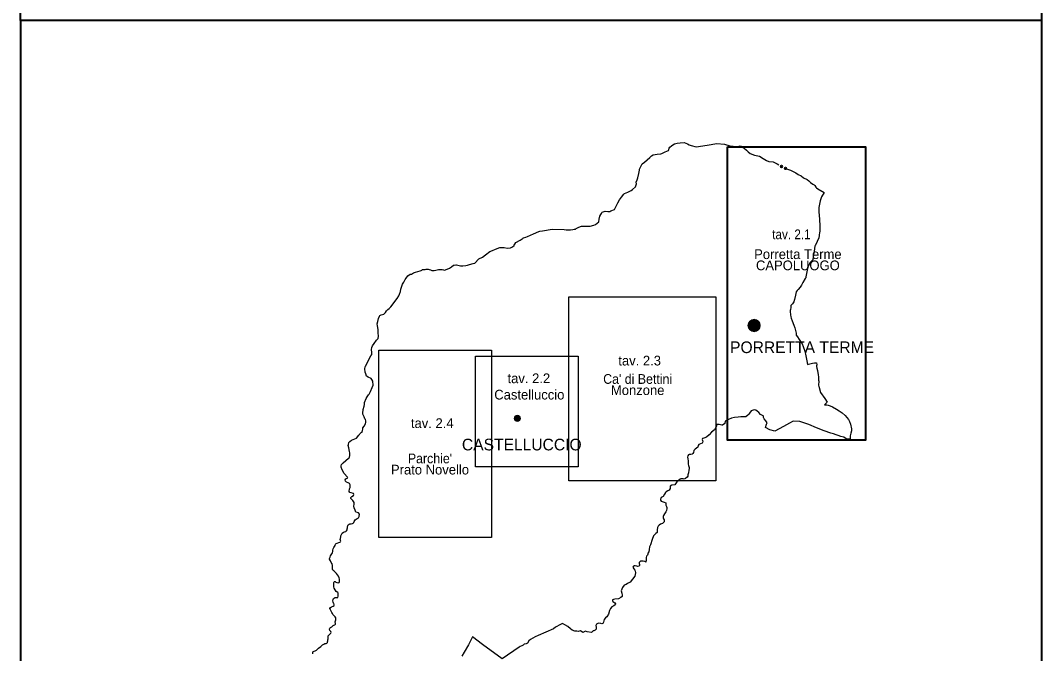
# Model space of a CAD drawing. Extents: x 654952 to 658955, y 890426 to 894481.
# Drawn here: x 654952 to 656002, y 892344 to 892994 of the extents above; entities that cross this region are included whole.
import ezdxf
from ezdxf.enums import TextEntityAlignment as Align

# ---------------------------------------------------------------- set-up
doc = ezdxf.new("R2010")
doc.units = 0
doc.header["$LTSCALE"] = 4
doc.header["$PDMODE"] = 32
doc.header["$PDSIZE"] = 2
doc.layers.add('60', color=7, linetype='Continuous', lineweight=35)

msp = doc.modelspace()

# ---------------------------------------------------------------- hatches: boundary and pattern name
at = {"layer": '60'}
for points in [[(655712.93, 892680.92, 1), (655700.21, 892680.92, 1)], [(655466.32, 892585.43, 1), (655459.96, 892585.43, 1)]]:
    msp.add_hatch(color=256, dxfattribs=at).paths.add_polyline_path(points)

# ---------------------------------------------------------------- linework, layer by layer
at = {"layer": '60', "lineweight": 40}
for p, q in [((654952.15, 892994.48), (654952.15, 890425.88)), ((656002.15, 892994.48), (656002.15, 890425.88))]:
    msp.add_line(p, q, dxfattribs=at)
for points in [[(656002.16, 894480.73), (656002.16, 892994.48), (654952.16, 892994.48), (654952.16, 894480.73)], [(655679.1, 892864.47), (655821.19, 892864.47), (655821.19, 892562.94), (655679.1, 892562.94)]]:
    msp.add_lwpolyline(points, close=True, dxfattribs=at)
at = {"layer": '60', "lineweight": 25}
for points in [[(655584.45, 892823.6), (655585.67, 892826.68), (655585.43, 892828.31), (655586.45, 892830.79), (655586.97, 892832.8), (655588.11, 892837.24), (655588.71, 892840.72), (655588.71, 892841.76), (655590.09, 892844.31), (655591.57, 892847.08), (655593.99, 892848.64), (655599.29, 892853.67), (655601.07, 892855.27), (655602.93, 892856.43), (655606.73, 892856.88), (655610.49, 892857.48), (655611.67, 892857.71), (655615.05, 892859.43), (655618.37, 892860.87), (655619.19, 892863.04), (655619.97, 892864.15), (655621.47, 892865.43), (655622.95, 892866.59), (655624.79, 892867.48), (655627.29, 892868.36), (655630.63, 892868.71), (655634.61, 892869), (655638.05, 892867.56), (655639.95, 892866.71), (655641.71, 892865.99), (655646.85, 892864.59), (655658.25, 892866.28), (655668.21, 892867.92), (655676.23, 892867.47), (655681.53, 892865.52), (655684.87, 892865.27), (655689.69, 892864.91), (655692.33, 892865.47), (655693.29, 892865.4), (655694.19, 892865)], [(655694.19, 892865), (655695.09, 892864.39), (655696.41, 892863.15), (655698.65, 892861.04), (655700.37, 892859.35), (655702.65, 892857.87), (655706.85, 892856.16), (655712.25, 892855.04), (655715.85, 892852.63), (655719.39, 892850.47), (655721.85, 892849.32), (655726.11, 892849.03), (655730.19, 892847.12), (655731.83, 892845.95)], [(655738.93, 892842.44), (655743.87, 892840.64), (655747.47, 892838.75), (655749.57, 892837.72), (655751.97, 892836.28), (655754.79, 892834.67), (655757.49, 892832.8), (655761.03, 892830.96), (655762.95, 892829.52), (655764.49, 892827.83), (655766.97, 892826.32), (655768.35, 892825.56), (655768.89, 892824.72), (655770.05, 892823.04), (655770.57, 892822.52), (655772.15, 892821.51), (655778.61, 892817.76), (655776.03, 892813.08), (655775.19, 892811.23), (655774.49, 892809.12), (655773.21, 892802.16), (655773.27, 892797.16), (655773.59, 892794.72), (655773.75, 892789.6), (655773.91, 892787.72), (655774.13, 892785.31), (655774.11, 892778.2), (655773.69, 892775.79), (655773.53, 892774.55), (655773.47, 892773.15), (655773.27, 892771.39), (655773.11, 892770.87), (655771.53, 892767.36), (655769.45, 892762.68), (655769.03, 892762.6), (655768.29, 892757.32), (655767.99, 892755.75), (655767.79, 892753.47), (655767.35, 892751.23), (655767.03, 892749.24)], [(655486.17, 892777.83), (655489.09, 892778.35), (655498.79, 892779.88), (655511.17, 892779.51), (655513.21, 892779.36), (655517.61, 892779.15), (655520.11, 892779.6), (655521.59, 892780), (655522.91, 892780.07), (655523.73, 892780.76), (655526.49, 892782.03), (655529.09, 892782.88), (655530.45, 892783.12), (655532.97, 892783.19), (655536.29, 892783.19), (655538.13, 892783.19), (655541.65, 892784.2), (655543.43, 892784.68), (655545.03, 892786.08), (655547.01, 892787.56), (655547.37, 892790.32), (655548.03, 892793.28), (655548.97, 892795.12), (655549.77, 892796.19), (655550.43, 892797.4), (655553.33, 892798.44), (655556.19, 892798.2), (655558.27, 892798.15), (655559.41, 892798.72), (655562.85, 892800.04), (655564.35, 892802.83), (655566.49, 892806.87), (655568.09, 892810.03), (655570.11, 892812.87), (655572.61, 892815.92), (655573.39, 892816.48), (655576.83, 892818.12), (655579.99, 892819.8), (655581.65, 892820.55), (655584.45, 892823.6)], [(655388.37, 892737.79), (655390.95, 892738.79), (655393.31, 892739.83), (655395.29, 892741.39), (655397.33, 892742.92), (655398.21, 892743), (655399.95, 892743.28), (655400.59, 892743.24), (655404.53, 892742.12), (655405.17, 892742.12), (655406.91, 892742.39), (655410.21, 892742.63), (655411.95, 892743), (655413.99, 892743.55), (655417.55, 892744.55), (655419.33, 892745.08), (655423.53, 892749.31), (655427.43, 892751.28), (655430.49, 892753.44), (655434.75, 892757.04), (655437.57, 892757.92), (655440.75, 892759.27), (655445.01, 892761.12), (655445.71, 892761.16), (655449.53, 892761), (655452.79, 892760.44), (655456.23, 892760.75), (655458.21, 892761.67), (655459.87, 892763.04), (655459.81, 892763.52), (655460.57, 892764.64), (655461.73, 892766.07), (655465.93, 892768.48), (655469.01, 892770.64), (655469.23, 892771.19), (655471.95, 892771.55), (655473.45, 892772.32), (655479.69, 892775.04), (655485.35, 892777.55), (655486.17, 892777.83)], [(655767.03, 892749.24), (655766.83, 892748.55), (655765.89, 892747.56), (655764.89, 892746.48), (655764.25, 892745.6), (655763.51, 892744.55), (655762.51, 892742.24), (655761.97, 892740.88), (655761.27, 892737.95), (655760.59, 892734.51), (655759.85, 892730.83), (655759.59, 892730.03), (655759.05, 892729.12), (655756.79, 892725.11), (655755.21, 892722.39), (655753.85, 892720.4), (655751.75, 892717.87), (655750.85, 892716.75), (655749.83, 892715.52), (655749.07, 892712.11), (655748.05, 892707.76), (655747.41, 892705.15), (655745.89, 892703.31), (655744.47, 892701.39), (655744.47, 892701), (655744.41, 892699.32), (655743.85, 892697.23), (655743.59, 892696.24), (655743.71, 892695.31), (655743.97, 892691.91), (655744.23, 892689.99), (655744.73, 892688.56), (655745.69, 892685.84), (655747.29, 892681.44), (655748.43, 892678.67), (655749.97, 892673.15), (655749.97, 892672.39), (655749.71, 892671.15), (655751.13, 892669.36), (655752.91, 892666.63)], [(655339.59, 892708.6), (655341.21, 892711.39), (655341.97, 892713.12), (655342.85, 892716.03), (655343.43, 892718.28), (655344.19, 892721.24), (655345.13, 892723.55), (655346.23, 892725.52), (655347.75, 892728.12), (655348.83, 892729.68), (655350.39, 892731.91), (655353.05, 892733.52), (655354.21, 892733.76), (655355.23, 892734.39), (655356.25, 892735.12), (655358.31, 892735.75), (655363.09, 892737.24), (655364.31, 892737.6), (655364.81, 892737.96), (655365.63, 892738.6), (655366.29, 892738.6), (655367.47, 892738.35), (655368.17, 892738.35), (655369.45, 892738.79), (655371.57, 892738.92), (655372.53, 892738.6), (655373.67, 892738.11), (655375.27, 892737.6), (655376.49, 892737.36), (655377.57, 892737.36), (655379.23, 892737.72), (655380.63, 892738.11), (655382.17, 892738.48), (655383.37, 892738.55), (655384.15, 892738.55), (655385.73, 892738.35), (655387.21, 892738.23), (655388.37, 892737.79)], [(655314.39, 892623.75), (655313.37, 892625.55), (655312.75, 892626.6), (655309.55, 892627.83), (655308.03, 892628.68), (655307.37, 892631.36), (655306.75, 892633.03), (655306.41, 892636.36), (655306.67, 892638.36), (655307.07, 892639.23), (655312.49, 892649.88), (655313.45, 892651.12), (655313.49, 892651.95), (655313.37, 892653.19), (655313.05, 892656.11), (655313.63, 892658.28), (655314.21, 892660), (655315.93, 892662.28), (655318.41, 892665.76), (655320.01, 892667.68), (655320.39, 892670.04), (655320.15, 892673.44), (655319.89, 892676.92), (655319.19, 892680.44), (655319.11, 892682.56), (655319.49, 892685.16), (655320.21, 892688.2), (655321.23, 892690.63), (655321.73, 892691.07), (655323.15, 892691.8), (655325.75, 892692.6), (655326.57, 892693.11), (655327.53, 892694.28), (655328.61, 892695.88), (655329.83, 892697.51), (655331.37, 892698.56), (655333.15, 892699.99), (655335.57, 892703.2), (655337.31, 892705.44), (655339.59, 892708.6)], [(655752.91, 892666.63), (655755.83, 892661.92), (655756.85, 892659.27), (655758.71, 892654.56), (655759.73, 892649.87), (655760.87, 892644.59), (655761.45, 892640.92), (655762.59, 892641.28), (655766.73, 892642.28), (655768.79, 892642.67), (655770.57, 892642.55), (655771.01, 892640.36), (655770.83, 892639.44), (655770.69, 892638.88), (655771.15, 892637.2), (655771.71, 892634.68), (655772.17, 892632.44), (655772.43, 892630.47), (655772.67, 892627.99), (655772.93, 892624.59), (655773.13, 892623.6), (655772.81, 892619.68), (655772.99, 892618.36), (655773.45, 892617.63), (655773.39, 892617.07), (655774.97, 892612.12), (655779.39, 892605.8), (655781.61, 892602.11), (655778.97, 892599.36), (655780.39, 892599.31), (655781.39, 892599.4), (655782.75, 892599.08), (655784.79, 892598.39), (655787.05, 892597.36), (655791.39, 892594.95), (655793.99, 892593.32), (655797.13, 892591.16), (655800.05, 892588.56), (655802.03, 892586.24), (655803.69, 892584.32)], [(655290.97, 892550.04), (655290.65, 892551.52), (655289.69, 892555.12), (655289.31, 892557.72), (655289.37, 892558.59), (655290.01, 892560.64), (655290.91, 892561.68), (655292.57, 892563.12), (655295.89, 892564.48), (655297.73, 892565.16), (655300.17, 892568.12), (655300.87, 892568.88), (655301.31, 892569.55), (655302.53, 892570.8), (655303.41, 892571.23), (655303.55, 892572.04), (655303.93, 892573.03), (655304.07, 892574.52), (655304.31, 892575.88), (655305.53, 892577.6), (655306.95, 892579.91), (655307.25, 892581.59), (655307.25, 892582.8), (655306.95, 892584.16), (655306.43, 892585.16), (655305.53, 892587.04), (655304.25, 892589.83), (655304.13, 892590.95), (655304.63, 892594.55), (655305.59, 892598), (655306.05, 892599.68), (655305.99, 892601.67), (655307.63, 892605.88), (655308.79, 892607.75), (655310.07, 892609.67), (655310.83, 892610.32), (655312.11, 892613.19), (655313.77, 892617.08), (655314.99, 892619.76), (655314.39, 892623.75)], [(655703.39, 892593.28), (655701.69, 892590.96), (655701.15, 892589.64), (655700.01, 892588.6), (655698.23, 892587), (655697.21, 892586.95), (655693.97, 892587.03), (655692.81, 892586.95), (655690.03, 892586.56), (655686.43, 892586.28), (655683.15, 892585.63), (655680.17, 892584.44), (655676.77, 892582.68), (655676.37, 892580.04), (655674.19, 892578.44), (655673.25, 892578.64), (655670.73, 892579.19), (655668.33, 892579.24), (655667.47, 892576.87), (655665.83, 892573.76), (655662.91, 892571.32), (655660.19, 892568.64), (655657.67, 892566.32), (655655.01, 892565.2), (655653.35, 892564.63), (655653.09, 892563.59), (655653.57, 892562.79), (655653.89, 892561.2), (655653.29, 892560.15), (655651.39, 892559.36), (655649.61, 892558.56), (655649.13, 892557.64), (655648.73, 892555.87), (655647.49, 892554.76), (655645.97, 892553.87), (655645.11, 892553.2), (655644.57, 892552.31), (655644.27, 892550.44), (655643.59, 892549.36), (655642.85, 892548.71)], [(655803.69, 892584.32), (655804.59, 892582.35), (655805.61, 892579.68), (655806.87, 892574.84), (655806.75, 892572.79), (655806.13, 892570.43), (655805.45, 892567.36), (655805.17, 892564.55), (655803.15, 892563.96), (655801.23, 892564.6), (655798.93, 892566.07), (655795.87, 892566.84), (655793.15, 892567.92), (655790.97, 892568.56), (655788.19, 892569.68), (655785.39, 892570.43), (655778.61, 892572.6), (655770.71, 892575.63), (655762.83, 892579.08), (655753.71, 892582.32), (655746.63, 892582.44), (655743.11, 892580.47), (655736.85, 892577.19), (655727.75, 892572.48), (655722.87, 892573.83), (655718.31, 892576.08), (655719.41, 892579.48), (655720.09, 892580.95), (655718.67, 892583.04), (655717.03, 892585.03), (655716.21, 892586.48), (655716.21, 892587.8), (655715.87, 892587.95), (655713.29, 892589.52), (655711.33, 892591.63), (655709.69, 892592.95), (655708.33, 892594), (655706.97, 892594.2), (655705.51, 892593.95), (655703.39, 892593.28)], [(655298.31, 892488.84), (655297.11, 892489.2), (655296.21, 892491.27), (655295.25, 892493.48), (655294.93, 892495.28), (655295.37, 892497.4), (655295.37, 892498.88), (655293.85, 892500.99), (655291.93, 892502.96), (655291.75, 892504.03), (655292.83, 892505.03), (655294.61, 892506.07), (655295.07, 892507.36), (655294.49, 892508.24), (655292.31, 892508.92), (655290.71, 892509.28), (655290.27, 892510.28), (655290.53, 892512.88), (655291.17, 892514.32), (655291.05, 892517.07), (655290.39, 892518.67), (655289.25, 892519.28), (655287.47, 892519.79), (655286.31, 892521.03), (655285.93, 892522.27), (655286.69, 892523.39), (655288.29, 892523.92), (655288.81, 892524.36), (655288.35, 892525.12), (655285.11, 892528.96), (655282.87, 892532.43), (655281.79, 892535.4), (655281.79, 892536.83), (655282.47, 892538.2), (655283.87, 892539.88), (655286.75, 892542.16), (655289.49, 892544.4), (655290.57, 892545.28), (655290.91, 892547.68), (655290.97, 892550.04)], [(655642.85, 892548.71), (655641.45, 892548.32), (655639.93, 892548.28), (655639.25, 892548.08), (655638.51, 892547), (655638.13, 892545.76), (655638.41, 892543.96), (655638.87, 892541.99), (655638.93, 892540.4), (655638.93, 892538.32), (655639.07, 892537.08), (655639.41, 892536.04), (655639.71, 892535.07), (655639.71, 892533.79), (655639.55, 892532.36), (655638.97, 892529.52), (655638.33, 892527.36), (655638.39, 892525.92), (655637.71, 892524.99), (655636.13, 892523.84), (655634.67, 892523.15), (655633.55, 892523.28), (655631.21, 892523.28), (655630.39, 892522.95), (655628.33, 892521.35), (655627.11, 892520.24), (655625.07, 892517.32), (655621.85, 892516.95), (655620.33, 892515.67), (655620.29, 892513.35), (655619.37, 892511.75), (655617.75, 892510.88), (655616.25, 892510.03), (655615.37, 892509.27), (655614.31, 892507.47), (655613.03, 892505.2), (655612.21, 892504.72), (655611.13, 892504), (655610.55, 892503.27), (655610.31, 892502.4)], [(655610.31, 892502.4), (655610.35, 892501.51), (655611.09, 892500.28), (655611.91, 892500), (655613.97, 892499.43), (655615.71, 892498.63), (655615.91, 892497.07), (655615.95, 892496.11), (655616.49, 892494.95), (655616.79, 892493.8), (655616.79, 892492.91), (655616.45, 892490.68), (655615.81, 892489.31), (655614.59, 892487.51), (655613.47, 892485.72), (655613.07, 892484.52), (655613.13, 892483.35), (655613.53, 892482.28), (655614.13, 892481.27), (655613.93, 892479.16), (655613.05, 892477.95), (655612.23, 892477.47), (655610.43, 892476.84), (655609.05, 892475.76), (655607.93, 892474.59), (655607.25, 892473.36), (655606.81, 892470.79), (655606.91, 892468.24), (655605.49, 892467.24), (655604.03, 892465.64), (655603.25, 892464.71), (655601.83, 892461.04), (655599.87, 892455.32), (655599.15, 892453.47), (655598.77, 892450.79), (655598.27, 892448.36), (655597.41, 892447.08), (655597.15, 892445.8), (655596.87, 892445), (655595.85, 892443.96)], [(655274.55, 892452.84), (655275.75, 892454.64), (655276.29, 892456.07), (655276.89, 892456.87), (655277.85, 892457.36), (655279.43, 892457.91), (655280.73, 892458.27), (655281.33, 892458.64), (655281.45, 892459.12), (655281.27, 892460), (655280.97, 892461), (655281.13, 892462.15), (655281.51, 892463.64), (655281.57, 892464.63), (655281.93, 892465.47), (655283.13, 892467.36), (655284.51, 892468.48), (655285.53, 892468.96), (655286.91, 892469.31), (655287.57, 892469.92), (655287.99, 892470.84), (655288.23, 892471.79), (655288.39, 892472.91), (655288.47, 892474.36), (655288.77, 892475.04), (655289.19, 892475.91), (655290.05, 892476.6), (655290.91, 892477.12), (655292.15, 892477.15), (655293.63, 892477.27), (655294.29, 892477.72), (655295.01, 892478.56), (655295.35, 892479.51), (655296.45, 892481.2), (655298.49, 892482.48), (655299.85, 892483.32), (655300.61, 892484.56), (655300.75, 892486.84), (655299.67, 892488.52), (655298.31, 892488.84)], [(655275.69, 892409.36), (655274.77, 892410.91), (655274.35, 892412.36), (655274.37, 892413.2), (655274.37, 892415.04), (655274.41, 892416.72), (655274.61, 892417.56), (655275.15, 892417.8), (655275.79, 892417.68), (655276.53, 892417.27), (655277.55, 892416.75), (655279.11, 892416.47), (655280.01, 892416.8), (655280.35, 892417.72), (655280.41, 892418.83), (655280.19, 892420.2), (655279.87, 892421.64), (655279.11, 892423.31), (655278.21, 892424.59), (655277.25, 892426.04), (655275.87, 892427.44), (655274.55, 892428.87), (655273.47, 892429.39), (655273.07, 892430.04), (655273.13, 892430.92), (655273.19, 892432.39), (655272.97, 892434.4), (655272.57, 892436.07), (655271.73, 892437.47), (655270.89, 892439.08), (655269.87, 892440.63), (655269.91, 892441.36), (655270.61, 892442.76), (655271.13, 892444.32), (655271.57, 892445.31), (655273.03, 892447.31), (655273.39, 892448.51), (655273.31, 892450.08), (655273.73, 892451.35), (655274.55, 892452.84)], [(655595.85, 892443.96), (655595.59, 892442.44), (655595.69, 892441.12), (655595.69, 892439.76), (655595.19, 892437.8), (655594.07, 892438.36), (655592.43, 892438.76), (655590.71, 892438.8), (655589.73, 892438.67), (655588.95, 892438.04), (655588.47, 892437.24), (655588.41, 892436.44), (655588.67, 892435.35), (655588.67, 892434.36), (655587.93, 892433.51), (655586.57, 892433.32), (655585.83, 892433.56), (655584.33, 892434.07), (655583.11, 892434.03), (655582.41, 892433.56), (655582.03, 892432.6), (655582.23, 892431.72), (655582.87, 892430.67), (655583.93, 892429.44), (655584.23, 892428.79), (655584.63, 892426.71), (655583.85, 892423.4), (655581.69, 892420.28), (655579.25, 892417.15), (655576.53, 892415.83), (655574.85, 892414.88), (655573.01, 892413.95), (655571.35, 892411.67), (655569.79, 892408.16), (655570.57, 892405.91), (655570.87, 892403.8), (655570.87, 892402.39), (655569.69, 892401.36), (655567.17, 892400.12), (655563.45, 892399.56)], [(655275.99, 892374.91), (655275.75, 892375.72), (655275.75, 892376.35), (655275.99, 892377.43), (655276.41, 892378.48), (655276.61, 892379.35), (655276.33, 892380.39), (655275.81, 892381.4), (655274.63, 892382.67), (655273.95, 892383.36), (655273.35, 892383.96), (655272.97, 892384.92), (655272.37, 892386), (655271.73, 892387.36), (655270.87, 892388.76), (655270.51, 892389.4), (655270.45, 892389.72), (655270.45, 892390.19), (655270.95, 892391.16), (655271.85, 892391.88), (655273.61, 892392.56), (655274.63, 892393.12), (655274.83, 892393.91), (655274.43, 892395.11), (655274.15, 892395.64), (655273.77, 892396.67), (655273.41, 892398.04), (655273.71, 892399.24), (655274.13, 892400.31), (655274.95, 892401.08), (655275.75, 892401.47), (655276.61, 892401.48), (655277.89, 892401.35), (655278.39, 892401.52), (655278.85, 892402.63), (655279.01, 892403.92), (655278.91, 892405.88), (655278.47, 892406.48), (655276.81, 892407.67), (655275.69, 892409.36)], [(655563.45, 892399.56), (655561.89, 892399.47), (655561.01, 892399.08), (655560.81, 892398.12), (655561.21, 892397.28), (655563.45, 892395.76), (655564.13, 892395), (655563.85, 892393.79), (655562.49, 892392.92), (655560.23, 892391.8), (655558.77, 892390.19), (655557.81, 892387.96), (655556.75, 892384.28), (655555.29, 892381.55), (655553.73, 892380.6), (655552.47, 892378.71), (655551.87, 892376.04), (655551.09, 892374.72), (655550.13, 892374.35), (655548.95, 892374.52), (655547.01, 892374.83), (655545.83, 892374.63), (655544.67, 892373.96), (655543.69, 892372.64), (655544.07, 892370.76), (655544.17, 892368.87), (655543.29, 892367.8), (655541.63, 892367.24), (655541.13, 892366.96), (655539.49, 892365.27), (655534.89, 892366), (655533.25, 892366.79), (655530.37, 892365.44), (655527.93, 892367.24), (655525.69, 892366.39), (655524.13, 892366.79), (655522.17, 892366.68), (655519.65, 892367.8), (655517.69, 892369.24), (655514.95, 892371.4)], [(655252.75, 892343.52), (655252.75, 892344.52), (655252.87, 892345.44), (655253.37, 892345.95), (655254.27, 892346.2), (655255.35, 892346.68), (655256.45, 892347.31), (655257.61, 892348.12), (655258.73, 892349.44), (655260.97, 892351.16), (655262.69, 892352.8), (655264.05, 892353.55), (655265.01, 892354), (655266.37, 892354.19), (655267.13, 892354.51), (655267.81, 892355.27), (655268.07, 892355.84), (655268.13, 892356.84), (655268.41, 892357.72), (655268.57, 892358.76), (655268.51, 892359.95), (655268.49, 892361.11), (655268.71, 892362.04), (655269.17, 892362.79), (655270.59, 892364), (655271.35, 892364.68), (655271.55, 892365.48), (655271.21, 892366.48), (655270.33, 892367.52), (655269.97, 892368.8), (655270.23, 892369.68), (655270.83, 892370.36), (655272.37, 892371.11), (655273.07, 892371.76), (655273.77, 892372.48), (655274.55, 892372.87), (655275.39, 892373.11), (655275.87, 892373.55), (655275.99, 892374.12), (655275.99, 892374.91)], [(655514.95, 892371.4), (655511.93, 892373.31), (655509.69, 892374.63), (655507.65, 892373.59), (655502.37, 892370.76), (655500.13, 892369.32), (655492.41, 892365.64), (655484.61, 892362.24), (655481.31, 892360.92), (655476.63, 892358.35), (655474.87, 892356.95), (655473.43, 892354.36), (655472.07, 892353.84), (655470.13, 892353.24), (655469.05, 892352.27), (655467.69, 892351.6), (655466.05, 892351.12), (655464.83, 892350.4), (655447.49, 892338.48), (655427.31, 892353.16), (655417.01, 892360.84), (655413.01, 892352.84), (655408.31, 892345), (655405.95, 892341.12)]]:
    msp.add_lwpolyline(points, dxfattribs=at)
for points in [[(655515.92, 892710.4), (655667.24, 892710.4), (655667.24, 892521.38), (655515.92, 892521.38)], [(655436.62, 892655.48), (655436.62, 892463.04), (655320.52, 892463.04), (655320.52, 892655.48)], [(655420.21, 892649.39), (655525.72, 892649.39), (655525.72, 892535.53), (655420.21, 892535.53)]]:
    msp.add_lwpolyline(points, close=True, dxfattribs=at)
at = {"layer": '60', "lineweight": 13}
for centre, radius in [((655706.57, 892680.92), 6.36), ((655463.14, 892585.43), 3.18)]:
    msp.add_circle(centre, radius, dxfattribs=at)
at = {"layer": '60'}
for p in [(655734.75, 892844.44), (655738.93, 892842.44)]:
    msp.add_point(p, dxfattribs=at)

# ---------------------------------------------------------------- texts
at = {"layer": '60', "width": 0.9}
msp.add_text('tav. 2.1', height=10, dxfattribs=at).set_placement((655725.21, 892769.61))
at = {"layer": '60'}
for s, height, p in [('Porretta Terme', 10, (655751.58, 892749.23)), ('CAPOLUOGO', 10, (655751.57, 892737.73)), ('PORRETTA TERME', 12, (655755.86, 892652.56)), ('Castelluccio', 10, (655475.44, 892604.85)), ('Monzone', 10, (655586.84, 892609.47)), ('CASTELLUCCIO', 12, (655467.67, 892552.55)), ('Prato Novello', 10, (655373.29, 892527.8))]:
    msp.add_text(s, height=height, dxfattribs=at).set_placement(p, align=Align.CENTER)
for s, p in [('tav. 2.3', (655566.95, 892639.84)), ('tav. 2.2', (655453.01, 892621.66)), ('tav. 2.4', (655353.69, 892575.56))]:
    msp.add_text(s, height=10, dxfattribs=at).set_placement(p)
at = {"layer": '60', "width": 0.95}
for s, p in [("Ca' di Bettini", (655586.84, 892620.97)), ("Parchie'", (655373.29, 892539.3))]:
    msp.add_text(s, height=10, dxfattribs=at).set_placement(p, align=Align.CENTER)

doc.saveas('drawing.dxf')
